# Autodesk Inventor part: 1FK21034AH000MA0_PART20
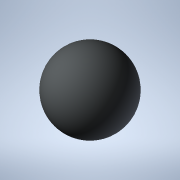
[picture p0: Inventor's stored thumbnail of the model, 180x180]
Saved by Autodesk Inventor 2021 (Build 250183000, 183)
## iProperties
Created: 2025-04
Part Number: 1FK21034AH000MA0_PART20
Material: Generic
Catalog Web Link: www.3dfindit.com
Description: -Servo synchronous motor
Document SubType Name: Modeling
Designer: psAdmin
Mass: 0.113097 g
Surface Area: 1.13097 cm^2
Volume: 0.113097 cm^3
Density: 1 g/cm^3
Appearance: PSOLRGB-212-217-219
Category: PARTsolutions
Title: 1FK21034AH000MA0_PART20
Author: Cadenas PARTsolutions
Comments: Servo synchronous motor
Sending System: PARTsolutions
Preprocessor: ST-DEVELOPER v19.3
PSOL_IDENT_0: {$CADENAS_DATA/23d-libs/siemens_ag/_cat_/ec/b7/1fk21034ah000ma0.prj},216 {VTYP=3D},{NB=1FK21034AH000
PSOL_IDENT_1: MA0_PART20},{LINA=1FK21034AH000MA0_PART20},{NN=1FK21034AH000MA0_PART20},{NOPRJ=TRUE},{DATE=19.08.202
PSOL_IDENT_2: 5 14:01:05},{GEOMDATE=30.07.2025 02:01:02},{VERSION=},{LINEID=10},{WBVAR=},{WBNUMERIC=}  {NB=1FK2103
PSOL_IDENT_3: 4AH000MA0_PART20},{LINA=1FK21034AH000MA0_PART20},{KT=DUMMY},{PREVIEW=../../../_pool_/7c/50/p_d211_xx
PSOL_IDENT_4: _00932j.png},{DESCSHORT=SIMOTICS S-1FK2 HD, SINAMICS S210 3AC 400V-480V, 1.01 Nm, 4500 rpm},{DESCLON
PSOL_IDENT_5: G=SIMOTICS S-1FK2 HD servo motor M0=1.27 Nm; PN = 0.48 kW at nN=4500 rpm (380-480 V); PN = 0.3 kW at
PSOL_IDENT_6: nN=2500 rpm (200-240 V); degree of protection IP64; cylindrical shaft D14 x 30 mm; absolute encoder
PSOL_IDENT_7: 22-bit + 12-bit multiturn (encoder AM22DQC); with OCC interface; plug size M17, rotatable; SIMOTICS
PSOL_IDENT_8: S-1FK2 servomotorfor a wide range of uses in industrial environments. SIMOTICS S‑1FK2 servomotors a
PSOL_IDENT_9: re compact synchronous motors with a high dynamic performance that set themselves apart as a result
PSOL_IDENT_10: of their high power density, degree of protection and overload capability. The motors are available
PSOL_IDENT_11: in two variants: as High Dynamic variant (highest dynamic performance as a result of the low intrins
PSOL_IDENT_12: ic moment of inertia for applications demanding a high dynamic performance with low moved masses) -
PSOL_IDENT_13: and as Compact variant (precise and stable closed-loop control for medium up to large moved masses a
PSOL_IDENT_14: s a result of a medium intrinsic moment of inertia). SIMOTICSS‑1FK2 servomotors fully exploit their
PSOL_IDENT_15: strengths in a system with the SINAMICSS210 frequency converter and simple connection using the one
PSOL_IDENT_16: cable connection (OCC). Advantages include the short control and positioning times, fast and precise
PSOL_IDENT_17: correction of disturbing quantities as well as stable control with a high dynamic performance. The
PSOL_IDENT_18: servo motors can be configured to address a wide range of requirements. For example with and without
PSOL_IDENT_19: holding brake, IP64 or IP65 degree of protection, singleturn or multiturn absolute encoders - to na
PSOL_IDENT_20: me just a few. Further, the servomotors are available in different shaft heights extending from 20 t
PSOL_IDENT_21: o 100. A shaft sealing ring is available to achieve an IP65 degree of protection and for subsequent
PSOL_IDENT_22: mounting at the motor or as spare part. SIMOTICS - the optimum motor for each and every motion contr
PSOL_IDENT_23: ol application.},{INTNO=4034106444822},{SUPPLIERALTNO=1FK2103-4AH00-0MA0},{MANUID=1FK21034AH000MA0},
PSOL_IDENT_24: {MANUNAME=Siemens},{MANUTYPEDESC=SYNCHRONOUS MOTOR 1FK2 HD 1,27 NM},{AAU732=SIMOTICS},{AAO057=S-1FK2
PSOL_IDENT_25: },{AAU734=SIMOTICS S-1FK2 HD servo motor M0=1.27 Nm; PN = 0.48 kW at nN=4500 rpm (380-480 V); PN = 0
PSOL_IDENT_26: .3 kW at nN=2500 rpm (200-240 V); degree of protection IP64; cylindrical shaft D14 x 30 mm; absolute
PSOL_IDENT_27: encoder 22-bit + 12-bit multiturn (encoder AM22DQC); with OCC interface; plug size M17, rotatable;}
PSOL_IDENT_28: ,{AAW338=SYNCHRONOUS MOTOR 1FK2 HD 1,27 NM},{AAO742=SIMOTICS},{AAO663=4034106444822},{NOCUPEROU=1},{
PSOL_IDENT_29: PRICEQUANTITY=1},{QUANTITYMIN=1},{QUANTITYINT=1},{CTN=85015100},{COO=RO},{AAO676=1FK2103-4AH00-0MA0}
PSOL_IDENT_30: ,{AAO677=Siemens AG},{ORDERUNIT=C62},{CONTENTUNIT=C62}
NB: 1FK21034AH000MA0_PART20
NT: Servo synchronous motor
NBSYN: $MANUID._PART20
LINA: 1FK21034AH000MA0_PART20
CATALOG: SIEMENS
PREVIEW: ../../../_pool_/7c/50/p_d211_xx_00932j.png
DESCSHORT: SIMOTICS S-1FK2 HD, SINAMICS S210 3AC 400V-480V, 1.01 Nm, 4500 rpm
DESCLONG: SIMOTICS S-1FK2 HD servo motor M0=1.27 Nm; PN = 0.48 kW at nN=4500 rpm (380-480 V); PN = 0.3 kW at nN=2500 rpm (200-240 V); degree of protection IP64; cylindric
INTNO: 4034106444822
SUPPLIERALTNO: 1FK2103-4AH00-0MA0
MANUID: 1FK21034AH000MA0
MANUNAME: Siemens
MANUTYPEDESC: SYNCHRONOUS MOTOR 1FK2 HD 1,27 NM
AAU732: SIMOTICS
AAO057: S-1FK2
AAU734: SIMOTICS S-1FK2 HD servo motor M0=1.27 Nm; PN = 0.48 kW at nN=4500 rpm (380-480 V); PN = 0.3 kW at nN=2500 rpm (200-240 V); degree of protection IP64; cylindric
AAW338: SYNCHRONOUS MOTOR 1FK2 HD 1,27 NM
AAO742: SIMOTICS
AAO663: 4034106444822.0
NOCUPEROU: 1
PRICEQUANTITY: 1
QUANTITYMIN: 1
QUANTITYINT: 1
CTN: 85015100
COO: RO
ARTICLENO: 1FK21034AH000MA0_PART20
BOMINFO: 1FK21034AH000MA0_PART20
CREATOR: CADENAS GmbH
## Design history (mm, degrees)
feature "2025_04_17_15_01_37_0314"
body "Solid1"
